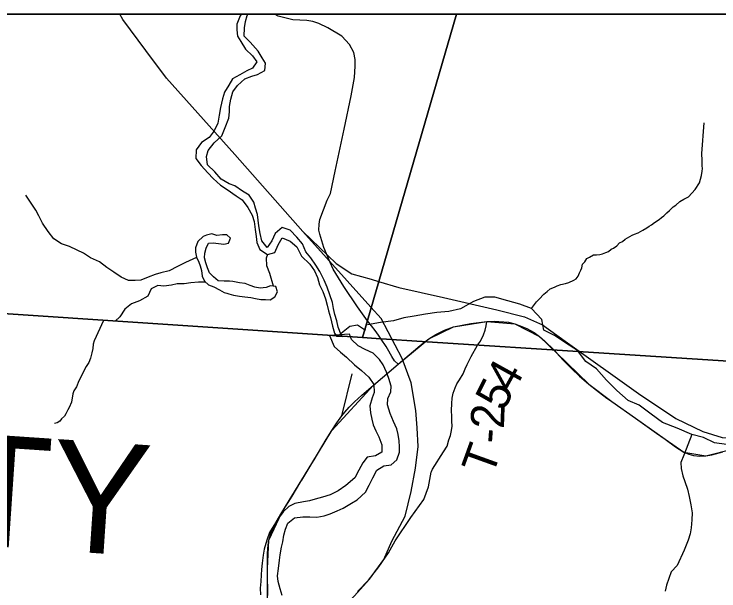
# Model space of a CAD drawing. Extents: x 0 to 82.7, y -0.2 to 22.
# Drawn here: x 5.374 to 6.574, y 19.918 to 20.9 of the extents above; entities that cross this region are included whole.
import ezdxf

# ---------------------------------------------------------------- set-up
doc = ezdxf.new("R2010")
doc.units = 0
for name, color, linetype in [('GM_X_County_Road', 7, 'Continuous'), ('GM_X_County_Text', 7, 'Continuous'), ('GM_X_Minor_Lake', 7, 'Continuous'), ('GM_X_Minor_River', 7, 'Continuous'), ('GM_X_Rail_Line', 7, 'Continuous'), ('GM_X_State_Route', 7, 'Continuous'), ('GM_X_Township_Road', 7, 'Continuous'), ('GM_X_Township_Road_Text', 7, 'Continuous'), ('GM_X_Township_Text', 7, 'Continuous'), ('SH_Cut_Line', 7, 'Continuous'), ('SH_Data', 7, 'Continuous'), ('SH_Text', 7, 'Continuous')]:
    doc.layers.add(name, color=color, linetype=linetype)

msp = doc.modelspace()

# ---------------------------------------------------------------- linework, layer by layer
at = {"layer": 'GM_X_County_Road'}
msp.add_line((5.9319, 20.2159), (5.9493, 20.2874), dxfattribs=at)
for points in [[(5.9759, 20.3777), (5.9589, 20.4014), (5.9352, 20.4364), (5.9174, 20.4655), (5.9123, 20.4768), (5.9015, 20.5026), (5.8943, 20.5255), (5.8929, 20.5323), (5.8932, 20.5425), (5.8943, 20.5503), (5.9069, 20.5832), (5.9126, 20.5947), (5.9204, 20.6327), (5.9357, 20.704), (5.9481, 20.7606), (5.9535, 20.7918), (5.9548, 20.8112), (5.9546, 20.8225), (5.9522, 20.8349), (5.9449, 20.8481), (5.932, 20.8624), (5.9083, 20.8769), (5.8927, 20.8839), (5.8827, 20.8874), (5.8722, 20.889), (5.8485, 20.8905), (5.8235, 20.8966), (5.8172, 20.9)], [(5.8055, 19.898), (5.8058, 19.9217), (5.8056, 19.9387), (5.8052, 19.9559), (5.8052, 19.9682), (5.8054, 19.9809), (5.806, 19.9898), (5.8066, 19.9958), (5.8079, 20.0042), (5.8098, 20.0116), (5.8111, 20.0155), (5.8127, 20.0198), (5.8146, 20.0242), (5.8171, 20.0292), (5.8204, 20.0351), (5.8299, 20.0512), (5.8473, 20.0794), (5.8624, 20.1042), (5.8639, 20.1065), (5.8809, 20.1346), (5.8848, 20.1413), (5.9055, 20.1755), (5.9151, 20.1911), (5.9235, 20.2043), (5.9319, 20.2159)]]:
    msp.add_lwpolyline(points, dxfattribs=at)
at = {"layer": 'GM_X_Minor_Lake'}
for points in [[(5.7462, 20.4449), (5.7405, 20.4455), (5.7314, 20.4451), (5.7215, 20.4459), (5.7132, 20.4528), (5.7068, 20.4596), (5.703, 20.468), (5.7004, 20.4763), (5.6982, 20.4851), (5.6986, 20.493), (5.7009, 20.5014), (5.7047, 20.5097), (5.713, 20.5108), (5.7217, 20.5096), (5.7312, 20.5081), (5.7392, 20.51), (5.7426, 20.5183), (5.7362, 20.5244), (5.7286, 20.524), (5.7188, 20.5233), (5.7108, 20.5256), (5.7017, 20.5238), (5.696, 20.5211), (5.6865, 20.5128), (5.6827, 20.5022), (5.6827, 20.4946), (5.6842, 20.4863), (5.6883, 20.4775), (5.6906, 20.4715), (5.6932, 20.4635), (5.6939, 20.454), (5.698, 20.4452), (5.7048, 20.4392), (5.7139, 20.4357), (5.7234, 20.4304), (5.7317, 20.4262), (5.736, 20.4249)], [(5.736, 20.4249), (5.7393, 20.4239), (5.7476, 20.4212), (5.7574, 20.4196), (5.7669, 20.4184), (5.7767, 20.4173), (5.7847, 20.4157), (5.7938, 20.4142), (5.8021, 20.4138), (5.8101, 20.4137), (5.818, 20.4186), (5.8226, 20.4273), (5.8196, 20.4364), (5.8105, 20.4376), (5.8029, 20.4346), (5.7931, 20.4335), (5.784, 20.4351), (5.7757, 20.4378), (5.7673, 20.4412), (5.7579, 20.4424), (5.7462, 20.4449)]]:
    msp.add_lwpolyline(points, dxfattribs=at)
at = {"layer": 'GM_X_Minor_River'}
for p, q in [((5.9448, 20.3551), (5.9109, 20.353)), ((5.9227, 20.3519), (5.9326, 20.3513))]:
    msp.add_line(p, q, dxfattribs=at)
for points in [[(5.7604, 20.9), (5.7587, 20.8968), (5.7533, 20.8828), (5.7533, 20.8733), (5.7544, 20.8627), (5.7601, 20.8532), (5.768, 20.8402), (5.7797, 20.8292), (5.7872, 20.8189), (5.7796, 20.8079), (5.7701, 20.8034), (5.7583, 20.7966), (5.7458, 20.7895), (5.7393, 20.7789), (5.7321, 20.7668), (5.729, 20.7558), (5.7252, 20.741), (5.7229, 20.7277), (5.7206, 20.7141), (5.7148, 20.7012), (5.7061, 20.6899), (5.6932, 20.6812), (5.6837, 20.6687), (5.6832, 20.6539), (5.6923, 20.6421)], [(5.7604, 20.9), (5.7587, 20.8968), (5.7533, 20.8828), (5.7533, 20.8733), (5.7544, 20.8627), (5.7601, 20.8532), (5.768, 20.8402), (5.7797, 20.8292), (5.7872, 20.8189), (5.7796, 20.8079), (5.7701, 20.8034), (5.7583, 20.7966), (5.7458, 20.7895), (5.7393, 20.7789), (5.7321, 20.7668), (5.729, 20.7558), (5.7252, 20.741), (5.7229, 20.7277), (5.7206, 20.7141), (5.7148, 20.7012), (5.7061, 20.6899), (5.6932, 20.6812), (5.6837, 20.6687), (5.6832, 20.6539), (5.6923, 20.6421)], [(5.7497, 20.6078), (5.7399, 20.6112), (5.7263, 20.6192), (5.7154, 20.6314), (5.7029, 20.6432), (5.7014, 20.6573), (5.7045, 20.6675), (5.7148, 20.6807), (5.7273, 20.6928), (5.7334, 20.7072), (5.7395, 20.7228), (5.7407, 20.7334), (5.7407, 20.7428), (5.7427, 20.755), (5.7461, 20.7675), (5.7541, 20.7785), (5.767, 20.7898), (5.7788, 20.7943), (5.7883, 20.7969), (5.8008, 20.8037), (5.802, 20.8162), (5.7963, 20.8257), (5.7892, 20.8367), (5.776, 20.852), (5.7654, 20.8622), (5.7662, 20.8767), (5.7681, 20.8873), (5.7708, 20.8979), (5.7725, 20.9)], [(6.2551, 20.3985), (6.2635, 20.4099), (6.2682, 20.4144), (6.2758, 20.4234), (6.2816, 20.4275), (6.2869, 20.432), (6.2942, 20.4349), (6.2988, 20.4375), (6.3049, 20.4394), (6.3129, 20.4415), (6.3186, 20.443), (6.327, 20.4471), (6.3308, 20.4493), (6.3346, 20.4538), (6.337, 20.4595), (6.3389, 20.464), (6.3405, 20.4678), (6.3421, 20.4742), (6.3459, 20.478), (6.349, 20.4837), (6.354, 20.4863), (6.3608, 20.49), (6.3658, 20.4903), (6.3711, 20.4906), (6.3757, 20.4917), (6.3814, 20.4939), (6.3859, 20.4957), (6.3909, 20.4995), (6.3947, 20.5017), (6.4005, 20.5054), (6.4047, 20.5103), (6.41, 20.5129), (6.4146, 20.517), (6.4185, 20.5193), (6.4265, 20.5237), (6.4307, 20.5252), (6.4368, 20.5274), (6.4444, 20.5319), (6.4513, 20.536), (6.4555, 20.5389), (6.4593, 20.5412), (6.4643, 20.5453), (6.4723, 20.5505), (6.4765, 20.5535), (6.4804, 20.5565), (6.4857, 20.5617), (6.4899, 20.5655), (6.4961, 20.5719), (6.5007, 20.5745), (6.5076, 20.5808), (6.5144, 20.5849), (6.5225, 20.589), (6.534, 20.6014), (6.5409, 20.6127), (6.5429, 20.6188), (6.5445, 20.6252), (6.5457, 20.6328), (6.5462, 20.637), (6.5458, 20.6416), (6.5459, 20.6469), (6.5456, 20.6507), (6.5453, 20.6625), (6.549, 20.7149)], [(5.6923, 20.6421), (5.7036, 20.63), (5.713, 20.6201), (5.7251, 20.6086), (5.7368, 20.6014), (5.752, 20.5903), (5.7622, 20.5835), (5.772, 20.5705), (5.7795, 20.5576), (5.7829, 20.5466), (5.7843, 20.5333), (5.7858, 20.5215), (5.7873, 20.5113), (5.7925, 20.4991), (5.8054, 20.4907), (5.8179, 20.4941), (5.8236, 20.507), (5.8305, 20.5191), (5.8441, 20.5134), (5.8554, 20.5038), (5.8633, 20.4879), (5.8773, 20.4742), (5.8856, 20.4631), (5.8905, 20.4513), (5.8942, 20.4392), (5.8995, 20.4278), (5.9044, 20.4153), (5.907, 20.4046), (5.9092, 20.3948), (5.9126, 20.3834), (5.916, 20.3686), (5.9197, 20.3568), (5.9227, 20.3519)], [(5.9326, 20.3513), (5.9311, 20.3541), (5.9258, 20.367), (5.9232, 20.3776), (5.9198, 20.3883), (5.9176, 20.3985), (5.9161, 20.4092), (5.9071, 20.435), (5.9018, 20.4471), (5.8943, 20.4616), (5.8875, 20.4726), (5.8792, 20.4852), (5.8709, 20.495), (5.8649, 20.5087), (5.8555, 20.5201), (5.8438, 20.5323), (5.8302, 20.5365), (5.8184, 20.5263), (5.8127, 20.5142), (5.8047, 20.5025), (5.7956, 20.5139), (5.793, 20.5264), (5.7908, 20.5393), (5.7893, 20.5492), (5.7886, 20.5587), (5.7852, 20.5693), (5.7818, 20.5796), (5.7739, 20.5918), (5.7626, 20.5986), (5.7497, 20.6078)], [(5.6845, 20.4856), (5.6656, 20.4772), (5.6519, 20.4705), (5.6379, 20.4629), (5.6238, 20.4596), (5.614, 20.4569), (5.6022, 20.4521), (5.5897, 20.4472), (5.5802, 20.4465), (5.5685, 20.4465), (5.5564, 20.4519), (5.5435, 20.4606), (5.5318, 20.4686), (5.5194, 20.4782), (5.5039, 20.4851), (5.4918, 20.4927), (5.4812, 20.498), (5.4683, 20.5042), (5.4543, 20.5091), (5.4415, 20.5172), (5.432, 20.5301), (5.4222, 20.5438), (5.4158, 20.5563), (5.4106, 20.5662), (5.4015, 20.5799), (5.3936, 20.5917)], [(5.8054, 20.4907), (5.8031, 20.4847), (5.8034, 20.4722), (5.8087, 20.4589), (5.8148, 20.4371)], [(5.7001, 20.4434), (5.6878, 20.4434), (5.6749, 20.4423), (5.6636, 20.4408), (5.6514, 20.4405), (5.6416, 20.4383), (5.6287, 20.4368), (5.6185, 20.438), (5.6071, 20.4323), (5.6014, 20.4198), (5.5873, 20.4119), (5.574, 20.4067), (5.5626, 20.3976), (5.5539, 20.3843), (5.5457, 20.3771)], [(6.5869, 20.1674), (6.5669, 20.1698), (6.548, 20.179), (6.5279, 20.1844), (6.5033, 20.1948), (6.4783, 20.2045), (6.4587, 20.2186), (6.4383, 20.2339), (6.4198, 20.242), (6.4002, 20.2592), (6.3829, 20.2767), (6.3656, 20.2962), (6.3478, 20.3084), (6.3336, 20.3275), (6.3128, 20.3401), (6.2943, 20.3528), (6.2761, 20.3616), (6.2725, 20.3798), (6.2551, 20.3985), (6.2351, 20.4059), (6.2147, 20.412), (6.1927, 20.4182), (6.1756, 20.4179), (6.1563, 20.4105), (6.1342, 20.3984), (6.114, 20.3936), (6.0939, 20.3922), (6.0746, 20.3892), (6.0552, 20.3859), (6.0377, 20.3826), (6.0199, 20.3777), (5.9979, 20.3748), (5.9754, 20.3708)], [(5.5259, 20.3782), (5.5101, 20.3438), (5.5085, 20.3381), (5.5077, 20.3305), (5.5061, 20.3233), (5.5041, 20.3142), (5.5009, 20.307), (5.4963, 20.2998), (5.4917, 20.2912), (5.4862, 20.2798), (5.4839, 20.2757), (5.48, 20.2655), (5.4757, 20.2583), (5.4738, 20.2534), (5.4713, 20.2394), (5.4678, 20.2303), (5.4651, 20.2261), (5.462, 20.2193), (5.4597, 20.2152), (5.4547, 20.2111), (5.4516, 20.2069), (5.447, 20.2039), (5.4425, 20.2029)], [(5.9304, 20.3559), (5.9341, 20.3594), (5.9455, 20.3685), (5.9584, 20.3711), (5.9705, 20.3631), (5.9722, 20.3627)], [(5.9109, 20.353), (5.9191, 20.3339), (5.9297, 20.3244), (5.94, 20.3157), (5.9533, 20.3031), (5.9654, 20.2932), (5.978, 20.2818), (5.9863, 20.2696), (5.9871, 20.2559), (5.9837, 20.2464), (5.9798, 20.2328), (5.981, 20.2213), (5.9829, 20.2103), (5.9855, 20.2004), (5.9897, 20.1902), (5.995, 20.1803), (6.0003, 20.1666), (5.9999, 20.1544), (5.9893, 20.148), (5.9752, 20.1457), (5.9676, 20.1362), (5.9608, 20.1236), (5.9539, 20.1103), (5.9387, 20.0974), (5.9258, 20.0883), (5.9121, 20.0815), (5.8992, 20.0773), (5.8866, 20.0739), (5.8767, 20.0712), (5.8668, 20.0697), (5.852, 20.0667), (5.8418, 20.0618), (5.8322, 20.0523), (5.8239, 20.042), (5.8159, 20.0291), (5.809, 20.0173), (5.8041, 20.0044), (5.7999, 19.9892), (5.798, 19.9789), (5.7961, 19.9652), (5.7953, 19.9546), (5.7945, 19.9451), (5.7942, 19.9341), (5.793, 19.9227), (5.7934, 19.9112)], [(5.8302, 19.9103), (5.8268, 19.9217), (5.8238, 19.9339), (5.8222, 19.9438), (5.8241, 19.9563), (5.8257, 19.97), (5.8268, 19.9795), (5.8291, 19.9921), (5.8314, 20.0016), (5.8329, 20.013), (5.836, 20.0233), (5.8398, 20.0335), (5.8516, 20.0422), (5.8653, 20.0441), (5.8774, 20.0438), (5.8896, 20.0437), (5.9021, 20.046), (5.912, 20.0494), (5.9238, 20.054), (5.9341, 20.0589), (5.9485, 20.0673), (5.958, 20.073), (5.9725, 20.0859), (5.9786, 20.0977), (5.985, 20.1102), (5.9915, 20.1235), (6.0037, 20.1311), (6.0158, 20.1326), (6.0257, 20.1413), (6.0299, 20.1539), (6.0299, 20.1634), (6.0295, 20.1733), (6.028, 20.1843), (6.0254, 20.1938), (6.0197, 20.2064), (6.014, 20.2201), (6.0098, 20.2345), (6.0102, 20.2455), (6.0152, 20.2569), (6.0159, 20.2664), (6.0121, 20.2798), (6.0083, 20.2904), (6.0023, 20.3026), (5.9962, 20.3121), (5.9852, 20.3227), (5.9715, 20.3292), (5.9597, 20.3353), (5.9483, 20.346), (5.9448, 20.3551)], [(6.5279, 20.1844), (6.5142, 20.1491), (6.5096, 20.1365), (6.51, 20.1263), (6.513, 20.1137), (6.5164, 20.1042), (6.5206, 20.0913), (6.5236, 20.0787), (6.5263, 20.0643), (6.5286, 20.051), (6.5278, 20.0388), (6.527, 20.0255), (6.5251, 20.0152), (6.5221, 20.0042), (6.5148, 19.9875), (6.503, 19.9613), (6.4931, 19.9503), (6.4889, 19.9389), (6.4851, 19.9275), (6.4825, 19.9176)]]:
    msp.add_lwpolyline(points, dxfattribs=at)
at = {"layer": 'GM_X_Rail_Line'}
msp.add_line((5.9815, 20.401), (5.8657, 20.5299), dxfattribs=at)
for points in [[(5.8657, 20.5299), (5.7499, 20.6607), (5.6336, 20.7911), (5.5982, 20.8378), (5.5589, 20.8906), (5.5538, 20.9)], [(5.8657, 20.5299), (5.9222, 20.4752), (5.9491, 20.4578), (5.9817, 20.4485), (5.9944, 20.4446)], [(5.9944, 20.4446), (6.0293, 20.4345), (6.1049, 20.4176), (6.1961, 20.3967), (6.2431, 20.3848), (6.2735, 20.3707), (6.3124, 20.3434), (6.437, 20.2541), (6.5007, 20.2115), (6.5467, 20.1893), (6.58, 20.1793), (6.5912, 20.1783), (6.6156, 20.1778), (6.6412, 20.1877), (6.6694, 20.2102), (6.6846, 20.24), (6.6992, 20.2769), (6.7153, 20.324)], [(5.3711, 19.3385), (5.4065, 19.3691), (5.6599, 19.6178), (5.9527, 19.9091), (5.9792, 19.9381), (6.0033, 19.9711), (6.017, 20.0025), (6.0401, 20.045), (6.0498, 20.0873), (6.0572, 20.1268), (6.062, 20.1637), (6.0603, 20.1953), (6.0579, 20.2249), (6.0498, 20.2719), (6.0348, 20.3135), (5.9987, 20.382), (5.9815, 20.401)]]:
    msp.add_lwpolyline(points, dxfattribs=at)
at = {"layer": 'GM_X_State_Route'}
for points in [[(6.0278, 20.3038), (6.0653, 20.3355), (6.0735, 20.3419), (6.0804, 20.3472), (6.0922, 20.3547), (6.1069, 20.3619), (6.1223, 20.3673), (6.1515, 20.3734), (6.179, 20.3766)], [(6.179, 20.3766), (6.1916, 20.3769), (6.1996, 20.3768), (6.208, 20.3763), (6.2157, 20.3753), (6.2265, 20.3727), (6.2387, 20.3683), (6.2468, 20.3647), (6.2593, 20.3579), (6.2686, 20.3512), (6.2779, 20.3433), (6.2936, 20.3277), (6.2977, 20.3232), (6.3091, 20.311), (6.323, 20.2965), (6.3365, 20.2833), (6.3524, 20.2697), (6.3706, 20.2555), (6.3835, 20.2463), (6.3919, 20.2405), (6.4324, 20.2119), (6.4681, 20.1866), (6.4826, 20.176), (6.5001, 20.1634), (6.5142, 20.1541), (6.5228, 20.1508), (6.5307, 20.1483), (6.5419, 20.1471), (6.5517, 20.1477), (6.5623, 20.1494), (6.5807, 20.1547)], [(5.9319, 20.2159), (5.9368, 20.2223), (5.9443, 20.2308), (5.9536, 20.2399), (5.9658, 20.251), (5.9857, 20.2681), (6.0278, 20.3038)], [(5.8055, 19.898), (5.8058, 19.9217), (5.8056, 19.9387), (5.8052, 19.9559), (5.8052, 19.9682), (5.8054, 19.9809), (5.806, 19.9898), (5.8066, 19.9958), (5.8079, 20.0042), (5.8098, 20.0116), (5.8111, 20.0155), (5.8127, 20.0198), (5.8146, 20.0242), (5.8171, 20.0292), (5.8204, 20.0351), (5.8299, 20.0512), (5.8473, 20.0794), (5.8624, 20.1042), (5.8639, 20.1065), (5.8809, 20.1346), (5.8848, 20.1413), (5.9055, 20.1755), (5.9151, 20.1911), (5.9235, 20.2043), (5.9319, 20.2159)]]:
    msp.add_lwpolyline(points, dxfattribs=at)
at = {"layer": 'GM_X_Township_Road'}
for points in [[(6.0096, 20.33), (6.0072, 20.3342), (5.9988, 20.3468), (5.9944, 20.3532), (5.9918, 20.3572), (5.9885, 20.3614), (5.9823, 20.369), (5.9759, 20.3777)], [(6.1051, 20.1548), (6.1113, 20.1646), (6.1141, 20.1749), (6.1168, 20.1824), (6.1184, 20.1882), (6.1198, 20.1976), (6.1192, 20.2076), (6.1191, 20.2146), (6.1185, 20.2249), (6.1192, 20.2371), (6.1198, 20.2461), (6.1218, 20.2547), (6.1249, 20.2638), (6.128, 20.2706), (6.1325, 20.2775), (6.1385, 20.2873), (6.1421, 20.2961), (6.1455, 20.3035), (6.1523, 20.3169), (6.1633, 20.3361), (6.168, 20.3434), (6.1733, 20.3541), (6.1759, 20.3616), (6.178, 20.3694), (6.179, 20.3766)], [(6.0278, 20.3038), (6.0215, 20.3097), (6.0172, 20.3169), (6.0096, 20.33)], [(5.9587, 19.917), (5.9776, 19.936), (5.9949, 19.9587), (6.0117, 19.9825), (6.0229, 20.003), (6.0497, 20.0427), (6.0717, 20.0736), (6.0793, 20.0949), (6.0843, 20.1198), (6.0848, 20.1213), (6.0865, 20.1252), (6.1051, 20.1548)]]:
    msp.add_lwpolyline(points, dxfattribs=at)
at = {"layer": 'GM_X_Township_Text'}
for points in [[(6.1272, 20.9), (2.1, 20.9), (2.1, 19.5964), (2.2742, 19.1826), (2.3145, 19.0873), (2.397, 18.8926), (2.4438, 18.782), (2.7199, 18.1299), (2.7784, 18.9951), (2.7788, 19.0007), (2.8288, 19.7415), (2.8645, 20.2693), (2.8645, 20.2703), (2.8651, 20.279), (2.884, 20.5583), (3.179, 20.5374), (3.6288, 20.5056), (5.9672, 20.3493), (5.9756, 20.3782)], [(8.9, 20.1381), (8.9, 20.9), (6.1272, 20.9), (5.9756, 20.3782), (5.9672, 20.3493), (5.9906, 20.3478), (6.0773, 20.3422), (6.1569, 20.3371), (6.2809, 20.329), (6.7144, 20.301), (6.9227, 20.2875), (7.9434, 20.2083), (8.3897, 20.1756)]]:
    msp.add_lwpolyline(points, close=True, dxfattribs=at)
msp.add_lwpolyline([(8.9, 14.1), (8.9, 20.1381), (8.3897, 20.1756), (7.9434, 20.2083), (6.9227, 20.2875), (6.7144, 20.301), (6.2809, 20.329), (6.1569, 20.3371), (6.0773, 20.3422), (5.9906, 20.3478), (5.9672, 20.3493), (3.6288, 20.5056)], dxfattribs=at)
at = {"layer": 'SH_Cut_Line'}
for points in [[(4.1209, 14.8338), (3.8036, 15.5496), (3.6125, 15.9807), (3.4071, 16.476), (3.2909, 16.7562), (3.0556, 17.2782), (3.0279, 17.3486), (2.7199, 18.1299), (2.7784, 18.9951), (2.7788, 19.0007), (2.8288, 19.7415), (2.8645, 20.2693), (2.8645, 20.2703), (2.8651, 20.279), (2.884, 20.5583), (3.179, 20.5374), (3.6288, 20.5056), (5.9672, 20.3493), (5.9756, 20.3782), (6.1272, 20.9), (2.1, 20.9), (2.1, 14.1)], [(8.9, 14.1), (8.9, 20.9), (6.1272, 20.9), (5.9756, 20.3782), (5.9672, 20.3493), (3.6288, 20.5056), (3.179, 20.5374), (2.884, 20.5583), (2.8651, 20.279), (2.8645, 20.2703), (2.8645, 20.2693), (2.8288, 19.7415), (2.7788, 19.0007), (2.7784, 18.9951), (2.7199, 18.1299), (3.0279, 17.3486), (3.0556, 17.2782), (3.2909, 16.7562), (3.4071, 16.476), (3.6125, 15.9807), (3.8036, 15.5496), (4.1209, 14.8338)]]:
    msp.add_lwpolyline(points, dxfattribs=at)
at = {"layer": 'SH_Data'}
msp.add_line((2.1, 20.9), (8.9, 20.9), dxfattribs=at)
at = {"layer": 'SH_Text'}
for p, q in [((6.1223, 20.3673), (6.179, 20.3766)), ((6.179, 20.3766), (6.2265, 20.3727)), ((6.2265, 20.3727), (6.2686, 20.3512)), ((6.0804, 20.3472), (6.1223, 20.3673)), ((6.0278, 20.3038), (6.0804, 20.3472)), ((6.2686, 20.3512), (6.2977, 20.3232)), ((6.2977, 20.3232), (6.3524, 20.2697)), ((5.9857, 20.2681), (6.0278, 20.3038)), ((5.9151, 20.1911), (5.9857, 20.2681)), ((6.3524, 20.2697), (6.3919, 20.2405)), ((6.3919, 20.2405), (6.4324, 20.2119)), ((6.4324, 20.2119), (6.4826, 20.176)), ((5.8809, 20.1346), (5.9151, 20.1911)), ((6.4826, 20.176), (6.5142, 20.1541)), ((6.5517, 20.1477), (6.5966, 20.1592)), ((6.5142, 20.1541), (6.5517, 20.1477)), ((5.8299, 20.0512), (5.8809, 20.1346)), ((5.8079, 20.0042), (5.8299, 20.0512)), ((5.8052, 19.9559), (5.8079, 20.0042)), ((5.8079, 20.0042), (5.8079, 20.0042)), ((5.8055, 19.898), (5.8052, 19.9559)), ((5.8052, 19.9559), (5.8052, 19.9559))]:
    msp.add_line(p, q, dxfattribs=at)

# ---------------------------------------------------------------- texts
at = {"layer": 'GM_X_County_Text'}
msp.add_text('LAWRENCE COUNTY', height=0.189394, rotation=356.1322, dxfattribs=at).set_placement((3.0295, 20.1501))
at = {"layer": 'GM_X_Township_Road_Text'}
for s, rotation, p in [('4', 61.0523, (6.2231, 20.2529)), ('5', 63.4396, (6.2077, 20.2221)), ('2', 87.977, (6.208, 20.1933)), ('-', 85.7957, (6.2062, 20.1677)), ('T', 70.1805, (6.1883, 20.1113))]:
    msp.add_text(s, height=0.0568, rotation=rotation, dxfattribs=at).set_placement(p)

doc.saveas('drawing.dxf')
